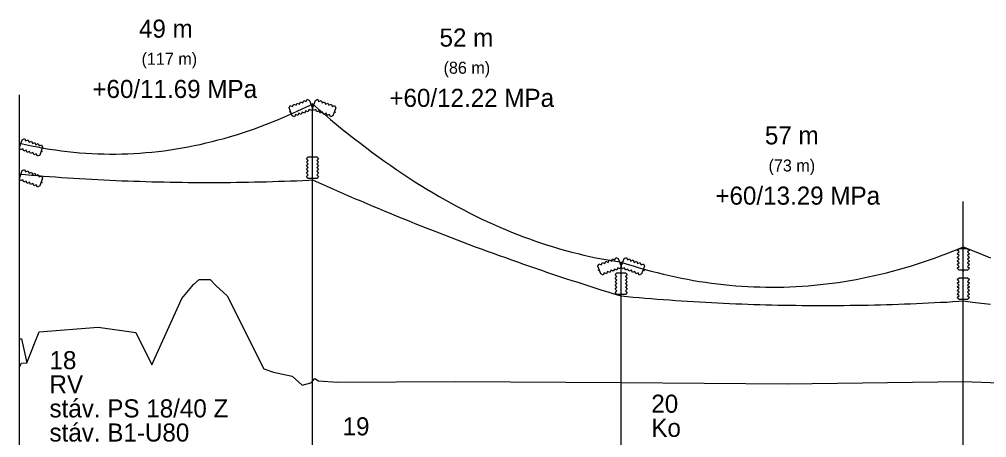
# Model space of a CAD drawing. Extents: x -21 to 1498, y 791 to 988.
# Drawn here: x 0 to 160.5, y 909.8 to 979.2 of the extents above; entities that cross this region are included whole.
import ezdxf

# ---------------------------------------------------------------- set-up
doc = ezdxf.new("R2010")
doc.units = 0
for name, color, linetype in [('Vrstva 11', 7, 'Continuous'), ('Vrstva 12', 7, 'Continuous'), ('Vrstva 13', 7, 'Continuous'), ('Vrstva 14', 7, 'Continuous'), ('Vrstva 15', 7, 'Continuous'), ('Vrstva 29', 7, 'Continuous'), ('Vrstva 3', 7, 'Continuous')]:
    doc.layers.add(name, color=color, linetype=linetype)

msp = doc.modelspace()

# ---------------------------------------------------------------- linework, layer by layer
at = {"layer": 'Vrstva 11'}
for points in [[(0, 958.65), (1, 958.42), (2, 958.21), (3, 958.02), (4, 957.84), (5, 957.67), (6, 957.52), (7, 957.39), (8, 957.27), (9, 957.16), (10, 957.07), (11, 957), (12, 956.94), (13, 956.89), (14, 956.86), (15, 956.85), (16, 956.85), (17, 956.87), (18, 956.9), (19, 956.95), (20, 957.01), (21, 957.08), (22, 957.17), (23, 957.28), (24, 957.4), (25, 957.54), (26, 957.69), (27, 957.86), (28, 958.04), (29, 958.24), (30, 958.45), (31, 958.68), (32, 958.92), (33, 959.18), (34, 959.45), (35, 959.74), (36, 960.05), (37, 960.36), (38, 960.7), (39, 961.05), (40, 961.41), (41, 961.79), (42, 962.18), (43, 962.59), (44, 963.02), (45, 963.46), (46, 963.91), (47, 964.38), (48, 964.87), (48.62, 965.17)], [(48.62, 965.17), (49.62, 964.3), (50.62, 963.44), (51.62, 962.59), (52.62, 961.76), (53.62, 960.94), (54.62, 960.14), (55.62, 959.35), (56.62, 958.57), (57.62, 957.81), (58.62, 957.07), (59.62, 956.34), (60.62, 955.62), (61.62, 954.92), (62.62, 954.23), (63.62, 953.56), (64.62, 952.9), (65.62, 952.26), (66.62, 951.63), (67.62, 951.01), (68.62, 950.41), (69.62, 949.82), (70.62, 949.25), (71.62, 948.69), (72.62, 948.15), (73.62, 947.62), (74.62, 947.11), (75.62, 946.61), (76.62, 946.12), (77.62, 945.65), (78.62, 945.2), (79.62, 944.75), (80.62, 944.33), (81.62, 943.91), (82.62, 943.52), (83.62, 943.13), (84.62, 942.76), (85.62, 942.41), (86.62, 942.07), (87.62, 941.74), (88.62, 941.43), (89.62, 941.13), (90.62, 940.85), (91.62, 940.58), (92.62, 940.33), (93.62, 940.09), (94.62, 939.86), (95.62, 939.65), (96.62, 939.46), (97.62, 939.27), (98.62, 939.11), (99.62, 938.96), (99.83, 938.93)], [(0, 953.52), (1, 953.43), (2, 953.35), (3, 953.27), (4, 953.19), (5, 953.12), (6, 953.04), (7, 952.97), (8, 952.91), (9, 952.84), (10, 952.78), (11, 952.72), (12, 952.66), (13, 952.61), (14, 952.56), (15, 952.51), (16, 952.47), (17, 952.43), (18, 952.39), (19, 952.35), (20, 952.32), (21, 952.29), (22, 952.26), (23, 952.23), (24, 952.21), (25, 952.19), (26, 952.18), (27, 952.16), (28, 952.15), (29, 952.14), (30, 952.14), (31, 952.13), (32, 952.14), (33, 952.14), (34, 952.14), (35, 952.15), (36, 952.16), (37, 952.18), (38, 952.2), (39, 952.22), (40, 952.24), (41, 952.26), (42, 952.29), (43, 952.32), (44, 952.36), (45, 952.39), (46, 952.43), (47, 952.47), (48, 952.52), (48.62, 952.55)], [(48.62, 952.55), (49.62, 952.1), (50.62, 951.66), (51.62, 951.22), (52.62, 950.78), (53.62, 950.35), (54.62, 949.91), (55.62, 949.48), (56.62, 949.06), (57.62, 948.63), (58.62, 948.21), (59.62, 947.79), (60.62, 947.38), (61.62, 946.97), (62.62, 946.56), (63.62, 946.15), (64.62, 945.74), (65.62, 945.34), (66.62, 944.94), (67.62, 944.55), (68.62, 944.16), (69.62, 943.77), (70.62, 943.38), (71.62, 942.99), (72.62, 942.61), (73.62, 942.23), (74.62, 941.86), (75.62, 941.48), (76.62, 941.11), (77.62, 940.74), (78.62, 940.38), (79.62, 940.02), (80.62, 939.66), (81.62, 939.3), (82.62, 938.95), (83.62, 938.6), (84.62, 938.25), (85.62, 937.9), (86.62, 937.56), (87.62, 937.22), (88.62, 936.88), (89.62, 936.55), (90.62, 936.22), (91.62, 935.89), (92.62, 935.57), (93.62, 935.24), (94.62, 934.92), (95.62, 934.6), (96.62, 934.29), (97.62, 933.98), (98.62, 933.67), (99.62, 933.36), (99.83, 933.3)], [(99.83, 938.93), (100.83, 938.6), (101.83, 938.29), (102.83, 937.99), (103.83, 937.7), (104.83, 937.43), (105.83, 937.17), (106.83, 936.92), (107.83, 936.69), (108.83, 936.47), (109.83, 936.26), (110.83, 936.07), (111.83, 935.89), (112.83, 935.72), (113.83, 935.57), (114.83, 935.43), (115.83, 935.3), (116.83, 935.19), (117.83, 935.09), (118.83, 935), (119.83, 934.93), (120.83, 934.87), (121.83, 934.82), (122.83, 934.79), (123.83, 934.76), (124.83, 934.76), (125.83, 934.76), (126.83, 934.78), (127.83, 934.82), (128.83, 934.86), (129.83, 934.92), (130.83, 934.99), (131.83, 935.08), (132.83, 935.18), (133.83, 935.29), (134.83, 935.42), (135.83, 935.56), (136.83, 935.71), (137.83, 935.88), (138.83, 936.05), (139.83, 936.25), (140.83, 936.45), (141.83, 936.67), (142.83, 936.9), (143.83, 937.15), (144.83, 937.41), (145.83, 937.68), (146.83, 937.97), (147.83, 938.26), (148.83, 938.58), (149.83, 938.9), (150.83, 939.24), (151.83, 939.59), (152.83, 939.96), (153.83, 940.34), (154.83, 940.73), (155.83, 941.13), (156.59, 941.45)], [(156.59, 941.45), (158.09, 940.82), (159.59, 940.21), (161.09, 939.63)], [(99.83, 933.3), (100.83, 933.21), (101.83, 933.12), (102.83, 933.03), (103.83, 932.95), (104.83, 932.86), (105.83, 932.79), (106.83, 932.71), (107.83, 932.64), (108.83, 932.57), (109.83, 932.5), (110.83, 932.43), (111.83, 932.37), (112.83, 932.31), (113.83, 932.26), (114.83, 932.2), (115.83, 932.15), (116.83, 932.1), (117.83, 932.06), (118.83, 932.02), (119.83, 931.98), (120.83, 931.94), (121.83, 931.91), (122.83, 931.88), (123.83, 931.85), (124.83, 931.82), (125.83, 931.8), (126.83, 931.78), (127.83, 931.76), (128.83, 931.75), (129.83, 931.74), (130.83, 931.73), (131.83, 931.72), (132.83, 931.72), (133.83, 931.72), (134.83, 931.72), (135.83, 931.73), (136.83, 931.74), (137.83, 931.75), (138.83, 931.76), (139.83, 931.78), (140.83, 931.8), (141.83, 931.82), (142.83, 931.84), (143.83, 931.87), (144.83, 931.9), (145.83, 931.94), (146.83, 931.97), (147.83, 932.01), (148.83, 932.05), (149.83, 932.1), (150.83, 932.14), (151.83, 932.19), (152.83, 932.25), (153.83, 932.3), (154.83, 932.36), (155.83, 932.42), (156.59, 932.47)], [(156.59, 932.47), (158.09, 932.28), (159.59, 932.1), (161.09, 931.93)]]:
    msp.add_lwpolyline(points, dxfattribs=at)
at = {"layer": 'Vrstva 14'}
for p, q in [((0, 892.15), (0, 966.65)), ((48.62, 889.17), (48.62, 965.17)), ((156.59, 889.1), (156.59, 948.95)), ((99.83, 888.93), (99.83, 938.93))]:
    msp.add_line(p, q, dxfattribs=at)
at = {"layer": 'Vrstva 29'}
for points in [[(48.15, 965.75), (48.63, 964.43), (48.45, 964.05), (48.06, 964.23), (47.88, 963.84), (47.5, 964.02), (47.32, 963.64), (46.94, 963.82), (46.76, 963.43), (46.37, 963.61), (46.19, 963.23), (45.81, 963.41), (45.63, 963.02), (45.24, 963.2), (44.77, 964.52), (44.94, 964.9), (45.33, 964.72), (45.51, 965.11), (45.89, 964.93), (46.07, 965.31), (46.46, 965.13), (46.64, 965.52), (47.02, 965.34), (47.2, 965.72), (47.58, 965.54), (47.76, 965.93)], [(48.62, 964.43), (49.1, 965.75), (49.48, 965.93), (49.66, 965.54), (50.05, 965.72), (50.22, 965.34), (50.61, 965.52), (50.79, 965.13), (51.17, 965.31), (51.35, 964.93), (51.74, 965.11), (51.92, 964.72), (52.3, 964.9), (52.48, 964.52), (52, 963.2), (51.62, 963.02), (51.44, 963.41), (51.05, 963.23), (50.87, 963.61), (50.49, 963.43), (50.31, 963.82), (49.92, 963.64), (49.75, 964.02), (49.36, 963.84), (49.18, 964.23), (48.8, 964.05)], [(0, 957.91), (0.47, 959.22), (0.86, 959.4), (1.04, 959.02), (1.42, 959.2), (1.6, 958.81), (1.99, 958.99), (2.17, 958.61), (2.55, 958.79), (2.73, 958.4), (3.11, 958.58), (3.29, 958.2), (3.68, 958.38), (3.86, 957.99), (3.38, 956.68), (2.99, 956.5), (2.81, 956.88), (2.43, 956.7), (2.25, 957.09), (1.87, 956.91), (1.69, 957.29), (1.3, 957.11), (1.12, 957.5), (0.74, 957.32), (0.56, 957.7), (0.17, 957.52)], [(49.32, 952.8), (47.92, 952.8), (47.62, 953.1), (47.92, 953.4), (47.62, 953.7), (47.92, 954), (47.62, 954.3), (47.92, 954.6), (47.62, 954.9), (47.92, 955.2), (47.62, 955.5), (47.92, 955.8), (47.62, 956.1), (47.92, 956.4), (49.32, 956.4), (49.62, 956.1), (49.32, 955.8), (49.62, 955.5), (49.32, 955.2), (49.62, 954.9), (49.32, 954.6), (49.62, 954.3), (49.32, 954), (49.62, 953.7), (49.32, 953.4), (49.62, 953.1)], [(49.32, 952.8), (47.92, 952.8), (47.62, 953.1), (47.92, 953.4), (47.62, 953.7), (47.92, 954), (47.62, 954.3), (47.92, 954.6), (47.62, 954.9), (47.92, 955.2), (47.62, 955.5), (47.92, 955.8), (47.62, 956.1), (47.92, 956.4), (49.32, 956.4), (49.62, 956.1), (49.32, 955.8), (49.62, 955.5), (49.32, 955.2), (49.62, 954.9), (49.32, 954.6), (49.62, 954.3), (49.32, 954), (49.62, 953.7), (49.32, 953.4), (49.62, 953.1)], [(0, 952.78), (0.47, 954.09), (0.86, 954.27), (1.04, 953.89), (1.42, 954.07), (1.6, 953.68), (1.99, 953.86), (2.17, 953.48), (2.55, 953.66), (2.73, 953.27), (3.11, 953.45), (3.29, 953.07), (3.68, 953.25), (3.86, 952.86), (3.38, 951.55), (2.99, 951.37), (2.81, 951.75), (2.43, 951.57), (2.25, 951.96), (1.87, 951.78), (1.69, 952.16), (1.3, 951.98), (1.12, 952.37), (0.74, 952.19), (0.56, 952.57), (0.17, 952.39)], [(155.89, 941.2), (157.29, 941.2), (157.59, 940.9), (157.29, 940.6), (157.59, 940.3), (157.29, 940), (157.59, 939.7), (157.29, 939.4), (157.59, 939.1), (157.29, 938.8), (157.59, 938.5), (157.29, 938.2), (157.59, 937.9), (157.29, 937.6), (155.89, 937.6), (155.59, 937.9), (155.89, 938.2), (155.59, 938.5), (155.89, 938.8), (155.59, 939.1), (155.89, 939.4), (155.59, 939.7), (155.89, 940), (155.59, 940.3), (155.89, 940.6), (155.59, 940.9)], [(155.89, 941.2), (157.29, 941.2), (157.59, 940.9), (157.29, 940.6), (157.59, 940.3), (157.29, 940), (157.59, 939.7), (157.29, 939.4), (157.59, 939.1), (157.29, 938.8), (157.59, 938.5), (157.29, 938.2), (157.59, 937.9), (157.29, 937.6), (155.89, 937.6), (155.59, 937.9), (155.89, 938.2), (155.59, 938.5), (155.89, 938.8), (155.59, 939.1), (155.89, 939.4), (155.59, 939.7), (155.89, 940), (155.59, 940.3), (155.89, 940.6), (155.59, 940.9)], [(99.36, 939.5), (99.84, 938.18), (99.66, 937.8), (99.27, 937.98), (99.09, 937.59), (98.71, 937.77), (98.53, 937.39), (98.15, 937.57), (97.97, 937.18), (97.58, 937.36), (97.4, 936.98), (97.02, 937.16), (96.84, 936.77), (96.45, 936.95), (95.98, 938.27), (96.15, 938.65), (96.54, 938.47), (96.72, 938.86), (97.1, 938.68), (97.28, 939.06), (97.67, 938.88), (97.85, 939.27), (98.23, 939.09), (98.41, 939.47), (98.79, 939.29), (98.97, 939.68)], [(99.83, 938.18), (100.31, 939.5), (100.69, 939.68), (100.87, 939.29), (101.26, 939.47), (101.43, 939.09), (101.82, 939.27), (102, 938.88), (102.38, 939.06), (102.56, 938.68), (102.95, 938.86), (103.13, 938.47), (103.51, 938.65), (103.69, 938.27), (103.21, 936.95), (102.83, 936.77), (102.65, 937.16), (102.26, 936.98), (102.08, 937.36), (101.7, 937.18), (101.52, 937.57), (101.13, 937.39), (100.96, 937.77), (100.57, 937.59), (100.39, 937.98), (100.01, 937.8)], [(100.53, 933.55), (99.13, 933.55), (98.83, 933.85), (99.13, 934.15), (98.83, 934.45), (99.13, 934.75), (98.83, 935.05), (99.13, 935.35), (98.83, 935.65), (99.13, 935.95), (98.83, 936.25), (99.13, 936.55), (98.83, 936.85), (99.13, 937.15), (100.53, 937.15), (100.83, 936.85), (100.53, 936.55), (100.83, 936.25), (100.53, 935.95), (100.83, 935.65), (100.53, 935.35), (100.83, 935.05), (100.53, 934.75), (100.83, 934.45), (100.53, 934.15), (100.83, 933.85)], [(157.29, 932.72), (155.89, 932.72), (155.59, 933.02), (155.89, 933.32), (155.59, 933.62), (155.89, 933.92), (155.59, 934.22), (155.89, 934.52), (155.59, 934.82), (155.89, 935.12), (155.59, 935.42), (155.89, 935.72), (155.59, 936.02), (155.89, 936.32), (157.29, 936.32), (157.59, 936.02), (157.29, 935.72), (157.59, 935.42), (157.29, 935.12), (157.59, 934.82), (157.29, 934.52), (157.59, 934.22), (157.29, 933.92), (157.59, 933.62), (157.29, 933.32), (157.59, 933.02)]]:
    msp.add_lwpolyline(points, close=True, dxfattribs=at)
for points in [[(48.62, 965.17), (48.39, 965.09)], [(48.62, 965.17), (48.86, 965.09)], [(45, 963.86), (44.77, 963.77)], [(52.24, 963.86), (52.48, 963.77)], [(0, 958.65), (0.23, 958.56)], [(3.62, 957.33), (3.85, 957.25)], [(48.62, 956.4), (48.62, 956.65)], [(48.62, 956.4), (48.62, 956.65)], [(0, 953.52), (0.23, 953.44)], [(3.62, 952.2), (3.85, 952.12)], [(48.62, 952.55), (48.62, 952.8)], [(48.62, 952.55), (48.62, 952.8)], [(156.59, 941.45), (156.59, 941.2)], [(156.59, 941.45), (156.59, 941.2)], [(99.83, 938.93), (99.6, 938.84)], [(99.83, 938.93), (100.07, 938.84)], [(96.21, 937.61), (95.98, 937.52)], [(99.83, 937.15), (99.83, 937.4)], [(103.45, 937.61), (103.69, 937.52)], [(156.59, 937.6), (156.59, 937.35)], [(156.59, 937.6), (156.59, 937.35)], [(156.59, 936.32), (156.59, 936.57)], [(99.83, 933.3), (99.83, 933.55)], [(156.59, 932.47), (156.59, 932.72)]]:
    msp.add_lwpolyline(points, dxfattribs=at)
at = {"layer": 'Vrstva 3'}
for p, q in [((28.89, 935.2), (29.84, 936.05)), ((28.89, 935.2), (29.84, 936.05)), ((29.84, 936.05), (31.66, 936.05)), ((29.84, 936.05), (31.66, 936.05)), ((31.66, 936.05), (32.6, 935.05)), ((31.66, 936.05), (32.6, 935.05)), ((26.93, 932.9), (28.89, 935.2)), ((26.93, 932.9), (28.89, 935.2)), ((32.6, 935.05), (34.45, 933.35)), ((32.6, 935.05), (34.45, 933.35)), ((21.96, 921.9), (26.93, 932.9)), ((21.96, 921.9), (26.93, 932.9)), ((34.45, 933.35), (40.54, 921.2)), ((34.45, 933.35), (40.54, 921.2)), ((3.31, 927.35), (13.06, 928.15)), ((3.31, 927.35), (13.06, 928.15)), ((13.06, 928.15), (19.32, 927.25)), ((13.06, 928.15), (19.32, 927.25)), ((0, 926.2), (0.35, 926.2)), ((0.35, 926.2), (1.25, 922.2)), ((1.25, 922.2), (3.31, 927.35)), ((1.25, 922.2), (3.31, 927.35)), ((19.32, 927.25), (21.96, 921.9)), ((19.32, 927.25), (21.96, 921.9)), ((0, 921.52), (0.35, 922.15)), ((0.35, 922.15), (1.25, 922.2)), ((40.54, 921.2), (42.16, 920.65)), ((40.54, 921.2), (42.16, 920.65)), ((42.16, 920.65), (45.24, 920)), ((42.16, 920.65), (45.24, 920)), ((45.24, 920), (46.91, 918.5)), ((45.24, 920), (46.91, 918.5)), ((48.62, 919.17), (49.01, 919.6)), ((48.62, 919.17), (49.01, 919.6)), ((49.01, 919.6), (49.64, 919.2)), ((49.01, 919.6), (49.64, 919.2)), ((46.91, 918.5), (48.37, 918.9)), ((46.91, 918.5), (48.37, 918.9)), ((48.37, 918.9), (48.62, 919.17)), ((48.37, 918.9), (48.62, 919.17)), ((49.64, 919.2), (52.78, 919)), ((49.64, 919.2), (52.78, 919)), ((52.78, 919), (72.31, 919.1)), ((52.78, 919), (72.31, 919.1)), ((72.31, 919.1), (99.83, 918.93)), ((72.31, 919.1), (99.83, 918.93)), ((99.83, 918.93), (127.36, 918.75)), ((99.83, 918.93), (127.36, 918.75)), ((127.36, 918.75), (156.5, 919.1)), ((127.36, 918.75), (156.5, 919.1)), ((156.5, 919.1), (156.59, 919.1)), ((156.5, 919.1), (156.59, 919.1)), ((156.59, 919.1), (175.06, 918.45)), ((156.59, 919.1), (175.06, 918.45))]:
    msp.add_line(p, q, dxfattribs=at)

# ---------------------------------------------------------------- texts
at = {"layer": 'Vrstva 12'}
for s, p in [('+60/11.69 MPa', (12.11, 966.15)), ('+60/12.22 MPa', (61.38, 964.67)), ('+60/13.29 MPa', (115.46, 948.45))]:
    msp.add_text(s, height=3, dxfattribs=at).set_placement(p)
at = {"layer": 'Vrstva 13'}
for s, height, p in [('49 m', 3, (19.84, 976.15)), ('52 m', 3, (69.7, 974.67)), ('(117 m)', 2, (20.27, 971.65)), ('(86 m)', 2, (70.37, 970.17)), ('57 m', 3, (123.67, 958.45)), ('(73 m)', 2, (124.28, 953.95))]:
    msp.add_text(s, height=height, dxfattribs=at).set_placement(p)
at = {"layer": 'Vrstva 15'}
for s, p in [('18', (5, 921.15)), ('RV', (5, 917.15)), ('stáv. PS 18/40 Z', (5, 913.15)), ('20', (104.83, 913.93)), ('19', (53.62, 910.17)), ('stáv. B1-U80', (5, 909.15)), ('Ko', (104.83, 909.93))]:
    msp.add_text(s, height=3, dxfattribs=at).set_placement(p)

doc.saveas('drawing.dxf')
